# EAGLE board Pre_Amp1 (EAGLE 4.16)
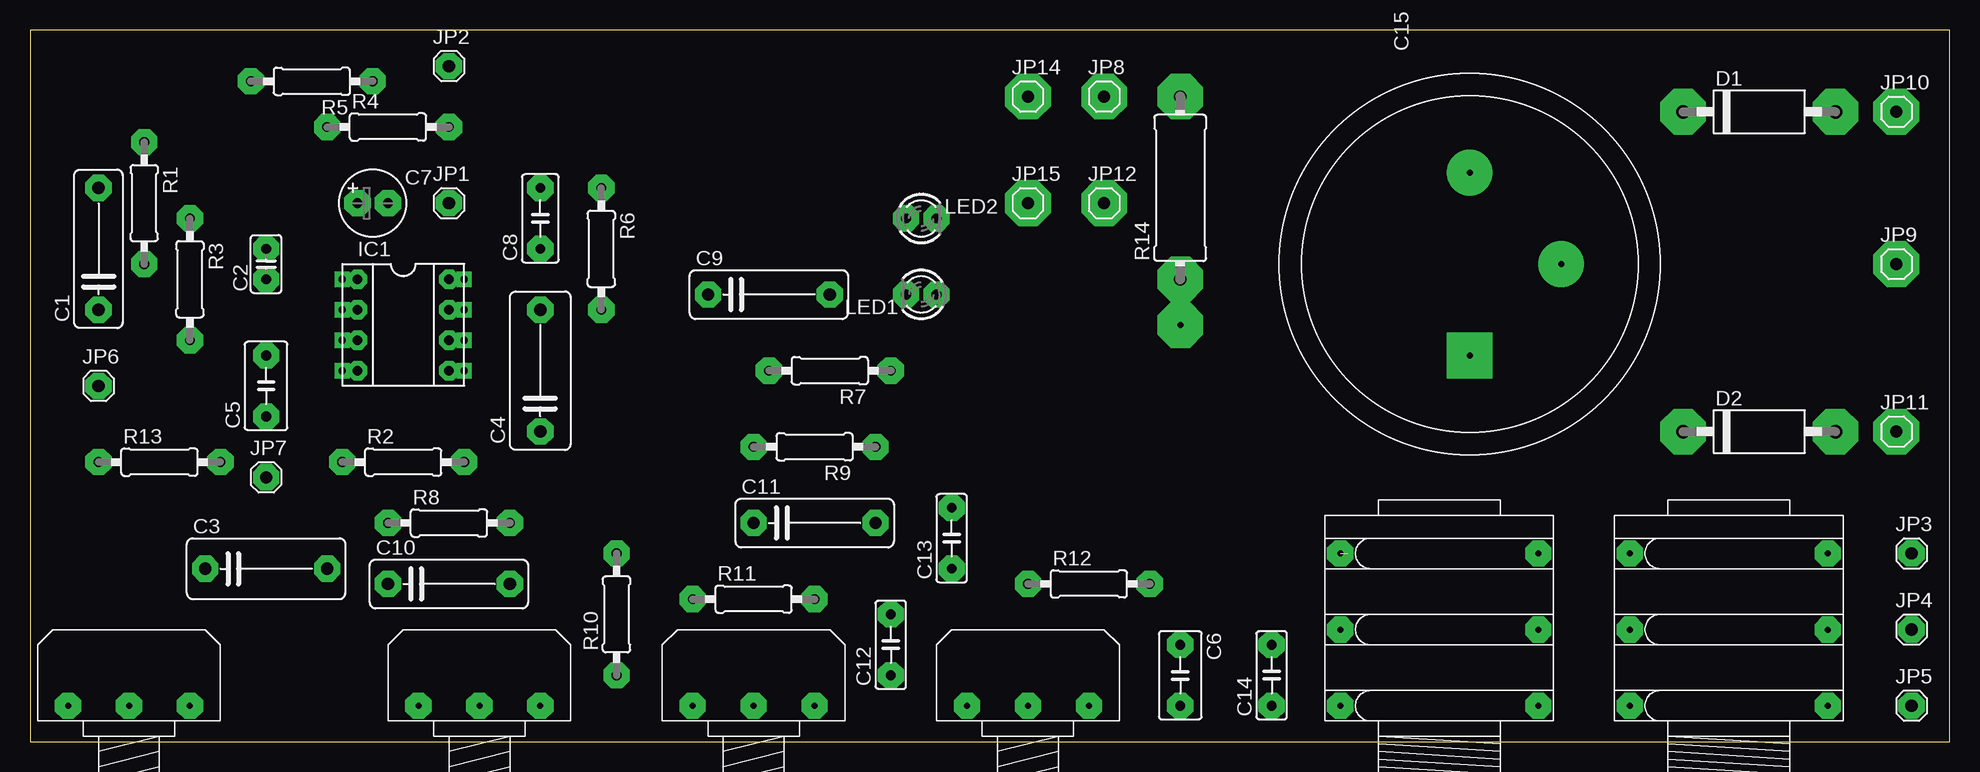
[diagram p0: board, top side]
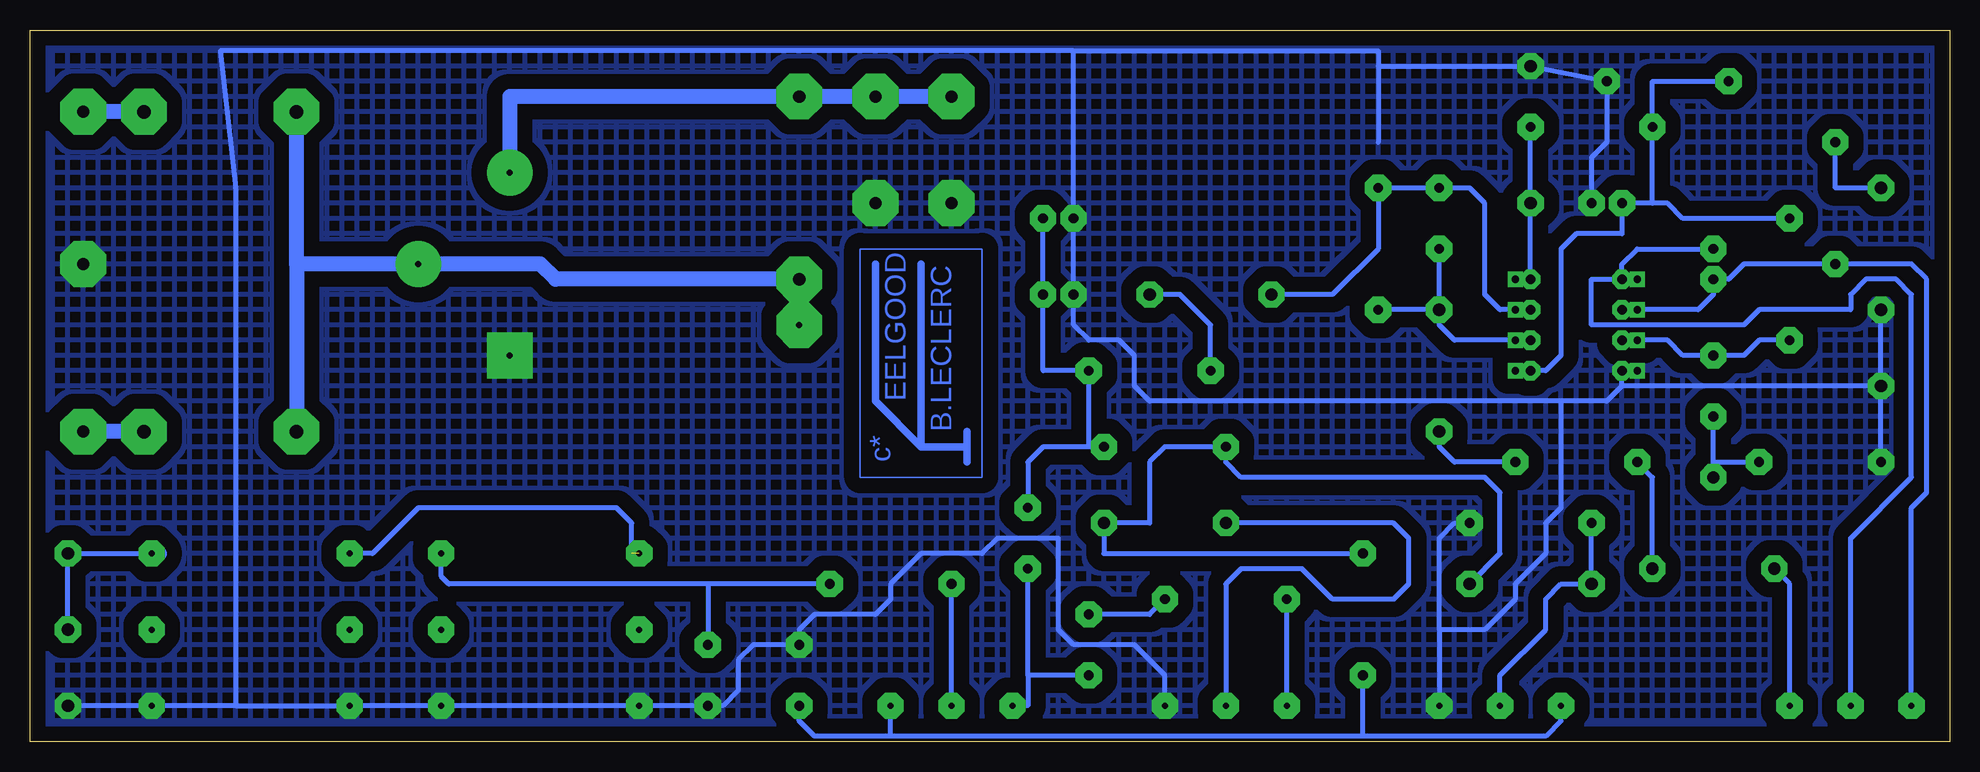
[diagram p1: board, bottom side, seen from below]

Size 160 x 59.36 mm. Coordinates in mm from the lower left corner, seen from the top.
Outline: 0,0 160,0 160,59.36 0,59.36 0,0
Copper layers (1*16): Top 0.035mm / dielectric 1.5mm / Bottom 0.035mm
Design rules "default": minimum track width 10mil, minimum drill 24mil, track to track 8mil, track to pad 8mil, pad to pad 8mil, via to via 8mil, smd to smd 8mil, copper to edge 40mil, drill to drill 8mil, minimum pad ring 10mil, minimum via ring 8mil, stop-mask expansion 4mil, vias tented up to drill 0mil, thermal gap 10mil

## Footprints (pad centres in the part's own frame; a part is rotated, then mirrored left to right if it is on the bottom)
C102-043X133 = drill 1.016 octagon: 1 -5.08,0; 2 5.08,0
C025-025X050 = drill 0.813 octagon: 1 -1.27,0; 2 1.27,0
C102-054X133 = drill 1.016 octagon: 1 -5.08,0; 2 5.08,0
C050-035X075 = drill 0.813 octagon: 1 -2.54,0; 2 2.54,0
E2,5-6 = drill 0.813 pad 1.6 round: + -1.27,0 | drill 0.813 pad 1.6 octagon: - 1.27,0
C050-030X075 = drill 0.813 octagon: 1 -2.54,0; 2 2.54,0
C050-025X075 = drill 0.813 octagon: 1 -2.54,0; 2 2.54,0
C-POL-X2 = drill 0.5 pad 3.81 square: 1 -7.62,0 | drill 0.5 pad 3.81 round: 2 0,-7.62; 3 7.62,0
DO15-12 = drill 1.118 long: A 6.35,0; C -6.35,0
DIL08 = drill 0.813 pad 1.6 octagon: 1 -3.81,-3.81; 2 -1.27,-3.81; 3 1.27,-3.81; 4 3.81,-3.81; 5 3.81,3.81; 6 1.27,3.81; 7 -1.27,3.81; 8 -3.81,3.81
JACK635 = drill 0.5 pad 2.184 octagon: 1 -8.255,6.35; 2 8.255,6.35; 3 -8.255,0; 4 8.255,0; 5 -8.255,-6.35; 6 8.255,-6.35
1X01 = drill 1.016 octagon: 1 0,0
LED3MM = drill 0.813 octagon: A -1.27,0; K 1.27,0
STD-EU = drill 0.5 pad 2.184 octagon: 1 -5.08,0; 2 0,0; 3 5.08,0
0207/10 = drill 0.813 octagon: 1 -5.08,0; 2 5.08,0
0414/15 = drill 1.016 octagon: 1 -7.62,0; 2 7.62,0

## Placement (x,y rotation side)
C1  100n  [C102-043X133]  5.71,41.11 90 top
C2  120p  [C025-025X050]  19.68,39.84 90 top
C3  150n  [C102-054X133]  19.68,14.44 0 top
C4  100n  [C102-054X133]  42.54,30.95 90 top
C5  10n  [C050-035X075]  19.68,29.68 90 top
C6  68n  [C050-035X075]  95.88,5.55 270 top
C7  10µ  [E2,5-6]  28.57,44.92 0 top
C8  220p  [C050-030X075]  42.54,43.65 90 top
C9  150n  [C102-043X133]  61.59,37.3 0 top
C10  100n  [C102-043X133]  34.92,13.17 0 top
C11  150n  [C102-043X133]  65.4,18.25 0 top
C12  10n  [C050-025X075]  71.75,8.09 90 top
C13  4n7  [C050-025X075]  76.83,16.98 90 top
C14  470p  [C050-025X075]  103.5,5.55 90 top
C15  6800µF/35V  [C-POL-X2]  120.01,39.84 90 top
D1  BY255  [DO15-12]  144.14,52.54 0 top
D2  BY255  [DO15-12]  144.14,25.87 0 top
IC1  TL082  [DIL08]  31.11,34.76 270 top
J2  Return  [JACK635]  141.6,9.36 180 top
J3  Send  [JACK635]  117.47,9.36 180 top
JP1  [1X01]  34.92,44.92 0 top
JP2  [1X01]  34.92,56.35 0 top
JP3  [1X01]  156.84,15.71 0 top
JP4  [1X01]  156.84,9.36 0 top
JP5  [1X01]  156.84,3.01 0 top
JP6  [1X01]  5.71,29.68 0 top
JP7  [1X01]  19.68,22.06 0 top
JP8  [1X01]  89.53,53.81 0 top
JP9  [1X01]  155.57,39.84 0 top
JP10  [1X01]  155.57,52.54 0 top
JP11  [1X01]  155.57,25.87 0 top
JP12  [1X01]  89.53,44.92 0 top
JP14  [1X01]  83.18,53.81 0 top
JP15  [1X01]  83.18,44.92 0 top
LED1  [LED3MM]  74.29,37.3 180 top
LED2  [LED3MM]  74.29,43.65 0 top
P1  100KBG  [STD-EU]  8.25,3.01 0 top
P3  10KAT  [STD-EU]  83.18,3.01 0 top
P4  10KAB  [STD-EU]  37.46,3.01 0 top
P5  10KAM  [STD-EU]  60.32,3.01 0 top
R1  2k2  [0207/10]  9.52,44.92 270 top
R2  10k  [0207/10]  31.11,23.33 0 top
R3  1M  [0207/10]  13.33,38.57 270 top
R4  47K  [0207/10]  29.84,51.27 0 top
R5  47K  [0207/10]  23.49,55.08 180 top
R6  680K  [0207/10]  47.62,41.11 270 top
R7  1K  [0207/10]  66.67,30.95 180 top
R8  680  [0207/10]  34.92,18.25 0 top
R9  1K5  [0207/10]  65.4,24.6 180 top
R10  680  [0207/10]  48.89,10.63 90 top
R11  100  [0207/10]  60.32,11.9 0 top
R12  22K  [0207/10]  88.26,13.17 0 top
R13  2M2  [0207/10]  10.79,23.33 0 top
R14  1/5W  [0414/15]  95.88,46.19 90 top
U$2  [LITTFEEL]  78.1,24.6 90 bottom

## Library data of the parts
C1-C15 R1-R14 = rcl
D1 D2 = diode
IC1 = burr-brown
J2 J3 = Con-Audio
JP1-JP12 JP14 JP15 = pinhead
LED1 LED2 = led
P1 P3-P5 = pot
U$2 = LOGO

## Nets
GND: C1.1 C6.1 C7.- C14.1 C15.1 IC1.4 J2.1 J2.2 J3.1 J3.2 JP2.1 JP5.1 JP6.1 JP9.1 JP12.1 JP15.1 LED1.K LED2.A P4.3 P5.3 R5.1 R8.2 R13.1
N$1: C1.2 R1.1
N$2: C2.1 IC1.2 P1.1 R1.2
N$3: C2.2 IC1.1 P1.2
N$4: C10.1 P4.2 R8.1
N$5: C5.1 JP7.1 R13.2
N$6: C5.2 IC1.3 R3.2
N$7: C6.2 P3.3 P4.1 R10.1
N$8: C3.1 P1.3
N$9: C3.2 R2.1
N$10: C4.1 R2.2
N$11: C4.2 C8.1 IC1.6 R6.2
N$13: C8.2 C9.1 IC1.7 R6.1
N$14: C9.2 R7.2
N$15: C13.2 LED1.A LED2.K R7.1 R9.1
N$16: P3.2 R12.1
N$17: C12.1 C13.1 P3.1
N$18: C12.2 R11.2
N$19: P5.1 R11.1
N$20: C11.1 P5.2
N$21: C10.2 C11.2 R9.2 R10.2
N$23: C14.2 J3.5 R12.2
N$28: J2.6 J3.6
N$29: J2.5 JP3.1 JP4.1
N$37: D1.A JP10.1
N$55: D2.A JP11.1
N$56: C15.2 D1.C D2.C R14.1
N$77: C15.3 JP8.1 JP14.1 R14.2
VCC: IC1.8 JP1.1 R4.2
VCC/2: C7.+ IC1.5 R3.1 R4.1 R5.2

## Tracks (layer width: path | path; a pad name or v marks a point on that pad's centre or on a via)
GND  (via drill 0.5 pad 2.18, 0.5 pad 3.81, 0.6 pad 1.27)
  Bottom 0.406: JP6.1 C1.1 | R13.1 JP6.1 | JP6.1 27.3,29.68 | 27.3,29.68 IC1.4 | C7.- 29.84,48.73 28.57,50 R5.1 JP2.1 47.62,56.35 | 32.38,28.41 28.57,28.41 27.3,29.68 | 32.38,28.41 66.67,28.41 67.94,29.68 67.94,32.22 69.21,33.49 71.75,33.49 73.02,34.76 LED1.K LED2.A 73.02,57.62 | 32.38,28.41 32.38,19.52 33.65,18.25 33.65,15.71 36.19,13.17 36.19,11.9 38.73,9.36 42.54,9.36 | R8.2 41.27,18.25 42.54,16.98 42.54,9.36 | 42.54,9.36 P4.3 | P5.3 65.4,5.55 67.94,8.09 73.02,8.09 74.29,9.36 74.29,16.98 79.37,16.98 80.64,15.71 85.72,15.71 88.26,13.17 88.26,11.9 89.53,10.63 94.61,10.63 95.88,9.36 C6.1 99.69,8.09 100.96,6.82 100.96,4.28 102.23,3.01 C14.1 108.58,3.01 | 108.58,3.01 109.85,3.01 | 108.58,3.01 J3.1 132.71,3.01 | 142.87,3.01 J2.2 | 142.87,3.01 149.22,3.01 | 149.22,3.01 150.49,3.01 | 149.22,3.01 JP5.1 | 73.02,57.62 144.14,57.62 142.87,46.19 142.87,3.01 | 47.62,56.35 47.62,57.62 73.02,57.62 | 47.62,56.35 47.62,50
  other vias: 156.84,3.01 103.5,3.01 95.88,8.09 5.71,36.03 5.71,29.68 5.71,23.33 34.92,56.35 28.57,55.08 29.84,44.92 73.02,37.3 73.02,43.65 40,18.25 26.03,30.95 89.53,44.92 155.57,39.84 83.18,44.92
  pour Bottom (isolate 1.27, no thermals, hatched): 0.63,0.47 0.63,58.89 159.38,58.89 159.38,0.47
N$1
  Bottom 0.406: C1.2 9.52,46.19 R1.1
N$2  (via drill 0.6 pad 1.27)
  Bottom 0.406: P1.1 3.17,19.52 1.9,20.79 1.9,38.57 3.17,39.84 R1.2 17.14,39.84 18.41,38.57 C2.1 19.68,37.3 20.95,36.03 v26.03,36.03 IC1.2
N$3
  Bottom 0.406: P1.2 8.25,16.98 3.17,22.06 3.17,37.3 4.44,38.57 6.98,38.57 8.25,37.3 8.25,36.03 15.87,36.03 17.14,34.76 29.84,34.76 29.84,38.57 IC1.1 27.3,39.84 26.03,41.11 C2.2
N$4
  Bottom 0.406: R8.1 C10.1 32.38,13.17 33.65,11.9 33.65,9.36 37.46,5.55 P4.2
N$5
  Bottom 0.406: JP7.1 19.68,23.33 | 19.68,23.33 C5.1 | 19.68,23.33 R13.2
N$6  (via drill 0.6 pad 1.27)
  Bottom 0.406: R3.2 15.87,33.49 17.14,32.22 C5.2 22.22,32.22 23.49,33.49 v26.03,33.49 IC1.3
N$7
  Bottom 0.406: P4.1 32.38,1.74 33.65,0.47 48.89,0.47 | 48.89,0.47 88.26,0.47 | 88.26,0.47 94.61,0.47 95.88,1.74 C6.2 | 48.89,0.47 R10.1 | 88.26,0.47 P3.3
N$8
  Bottom 0.406: P1.3 13.33,13.17 C3.1
N$9
  Bottom 0.406: C3.2 24.76,22.06 R2.1
N$10
  Bottom 0.406: R2.2 41.27,23.33 42.54,24.6 C4.1
N$11  (via drill 0.6 pad 1.27)
  Bottom 0.406: IC1.6 v36.19,33.49 41.27,33.49 42.54,34.76 C4.2 | C4.2 R6.2 | C4.2 C8.1
N$12  (via drill 0.5 pad 2.18)
  other vias: 56.51,37.3
N$13  (via drill 0.6 pad 1.27)
  Bottom 0.406: IC1.7 v36.19,36.03 37.46,36.03 38.73,37.3 38.73,44.92 40,46.19 C8.2 R6.1 47.62,41.11 51.43,37.3 C9.1
N$14
  Bottom 0.406: C9.2 64.13,37.3 61.59,34.76 R7.2
N$15
  Bottom 0.406: LED2.K LED1.A 75.56,30.95 R7.1 71.75,24.6 R9.1 75.56,24.6 76.83,23.33 C13.2
N$16
  Bottom 0.406: P3.2 R12.1
N$17
  Bottom 0.406: 76.83,5.55 76.83,3.01 P3.1 | 76.83,5.55 C13.1 | C12.1 76.83,5.55
N$18
  Bottom 0.406: C12.2 66.67,10.63 R11.2
N$19
  Bottom 0.406: P5.1 R11.1
N$20
  Bottom 0.406: C11.1 46.35,18.25 45.08,16.98 45.08,13.17 46.35,11.9 51.43,11.9 53.97,14.44 59.05,14.44 60.32,13.17 P5.2
N$21
  Bottom 0.406: R10.2 70.48,15.71 C11.2 66.67,18.25 66.67,23.33 65.4,24.6 R9.2 60.32,23.33 59.05,22.06 38.73,22.06 37.46,20.79 37.46,15.71 C10.2
N$22  (via drill 0.5 pad 2.18)
  other vias: 42.54,25.87
N$23
  Bottom 0.406: R12.2 103.5,13.17 | 103.5,13.17 C14.2 | J3.5 125.72,13.81 125.09,13.17 103.5,13.17
N$24  (via drill 0.5 pad 2.18)
  other vias: 42.54,36.03
N$25  (via drill 0.5 pad 2.18)
  other vias: 47.62,36.03
N$26  (via drill 0.5 pad 2.18)
  other vias: 47.62,46.19
N$27  (via drill 0.5 pad 2.18)
  other vias: 42.54,41.11
N$28  (1 unrouted)
  Bottom 0.406: 133.98,15.71 J2.6 131.44,15.71 127.63,19.52 111.12,19.52 109.85,18.25 109.85,15.71
N$29
  Bottom 0.406: JP4.1 JP3.1 J2.5
  Bottom 1.27: J2.5 149.22,15.71
N$30  (via drill 0.5 pad 2.18)
  other vias: 42.54,46.19
N$31  (via drill 0.5 pad 2.18)
  other vias: 19.68,22.06
N$32  (via drill 0.5 pad 2.18)
  other vias: 27.3,44.92
N$33  (via drill 0.6 pad 1.27)
  other vias: 26.03,38.57
N$34  (via drill 0.5 pad 2.18)
  other vias: 34.92,44.92
N$35  (via drill 0.5 pad 2.18)
  other vias: 34.92,51.27
N$36  (via drill 0.5 pad 2.18)
  other vias: 24.76,51.27
N$37
  Bottom 1.27: D1.A JP10.1
N$38  (via drill 0.6 pad 1.27)
  other vias: 36.19,30.95
N$39  (via drill 0.5 pad 2.18)
  other vias: 18.41,55.08
N$40  (via drill 0.5 pad 2.18)
  other vias: 19.68,38.57
N$41  (via drill 0.5 pad 2.18)
  other vias: 19.68,41.11
N$42  (via drill 0.5 pad 2.18)
  other vias: 13.33,43.65
N$43  (via drill 0.5 pad 2.18)
  other vias: 13.33,33.49
N$44  (via drill 0.5 pad 2.18)
  other vias: 9.52,39.84
N$45  (via drill 0.5 pad 2.18)
  other vias: 9.52,50
N$46  (via drill 0.5 pad 2.18)
  other vias: 5.71,46.19
N$47  (via drill 0.5 pad 2.18)
  other vias: 19.68,32.22
N$48  (via drill 0.5 pad 2.18)
  other vias: 19.68,27.14
N$49  (via drill 0.6 pad 1.27)
  other vias: 36.19,38.57
N$50  (via drill 0.5 pad 2.18)
  other vias: 29.84,13.17
N$51  (via drill 0.5 pad 2.18)
  other vias: 24.76,14.44
N$52  (via drill 0.5 pad 2.18)
  other vias: 14.6,14.44
N$53  (via drill 0.5 pad 2.18)
  other vias: 40,13.17
N$54  (via drill 0.5 pad 2.18)
  other vias: 29.84,18.25
N$55
  Bottom 1.27: D2.A JP11.1
N$56
  Bottom 1.27: R14.1 116.2,38.57 117.47,39.84 C15.2 137.79,39.84 | 137.79,39.84 D2.C | 137.79,39.84 D1.C
N$57  (via drill 0.5 pad 2.18)
  other vias: 15.87,23.33
N$58  (via drill 0.5 pad 2.18)
  other vias: 66.67,37.3
N$59  (via drill 0.5 pad 2.18)
  other vias: 93.34,13.17
N$60  (via drill 0.5 pad 2.18)
  other vias: 83.18,13.17
N$61  (via drill 0.5 pad 2.18)
  other vias: 71.75,5.55
N$62  (via drill 0.5 pad 2.18)
  other vias: 71.75,10.63
N$63  (via drill 0.5 pad 2.18)
  other vias: 65.4,11.9
N$64  (via drill 0.5 pad 2.18)
  other vias: 55.24,11.9
N$65  (via drill 0.5 pad 2.18)
  other vias: 76.83,14.44
N$66  (via drill 0.5 pad 2.18)
  other vias: 48.89,5.55
N$67  (via drill 0.5 pad 2.18)
  other vias: 70.48,18.25
N$68  (via drill 0.5 pad 2.18)
  other vias: 60.32,24.6
N$69  (via drill 0.5 pad 2.18)
  other vias: 76.83,19.52
N$70  (via drill 0.5 pad 2.18)
  other vias: 48.89,15.71
N$71  (via drill 0.5 pad 2.18)
  other vias: 60.32,18.25
N$72  (via drill 0.5 pad 2.18)
  other vias: 71.75,30.95
N$73  (via drill 0.5 pad 2.18)
  other vias: 61.59,30.95
N$74  (via drill 0.5 pad 2.18)
  other vias: 70.48,24.6
N$75  (via drill 0.5 pad 2.18)
  other vias: 36.19,23.33
N$76  (via drill 0.5 pad 2.18)
  other vias: 26.03,23.33
N$77
  Bottom 1.27: C15.3 120.01,53.81 R14.2 JP8.1 JP14.1
N$78  (via drill 0.5 pad 2.18)
  other vias: 103.5,8.09
N$79  (via drill 0.5 pad 2.18)
  other vias: 95.88,3.01
N$80  (via drill 0.5 pad 3.81)
  other vias: 89.53,53.81
N$81  (via drill 0.5 pad 2.18)
  other vias: 75.56,37.3
N$82  (via drill 0.5 pad 3.81)
  other vias: 83.18,53.81
N$83  (via drill 0.5 pad 2.18)
  other vias: 75.56,43.65
N$84  (via drill 0.5 pad 3.81)
  other vias: 95.88,53.81
N$85  (via drill 0.5 pad 2.18)
  other vias: 156.84,15.71
N$86  (via drill 0.5 pad 2.18)
  other vias: 156.84,9.36
N$87  (via drill 0.5 pad 3.81)
  other vias: 95.88,38.57
N$88  (via drill 0.5 pad 3.81)
  other vias: 137.79,52.54
N$89  (via drill 0.5 pad 3.81)
  other vias: 150.49,52.54
N$90  (via drill 0.5 pad 3.81)
  other vias: 137.79,25.87
N$91  (via drill 0.5 pad 3.81)
  other vias: 155.57,52.54
N$92  (via drill 0.5 pad 3.81)
  other vias: 150.49,25.87
N$93  (via drill 0.5 pad 3.81)
  other vias: 155.57,25.87
N$94  (via drill 0.5 pad 3.81)
  other vias: 95.88,34.76
VCC
  Bottom 0.406: R4.2 JP1.1 IC1.8
VCC/2
  Bottom 0.406: R3.1 22.22,43.65 23.49,44.92 24.76,44.92 | 24.76,44.92 C7.+ 27.3,42.38 31.11,42.38 32.38,41.11 32.38,32.22 33.65,30.95 IC1.5 | 24.76,44.92 R4.1 24.76,55.08 R5.2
